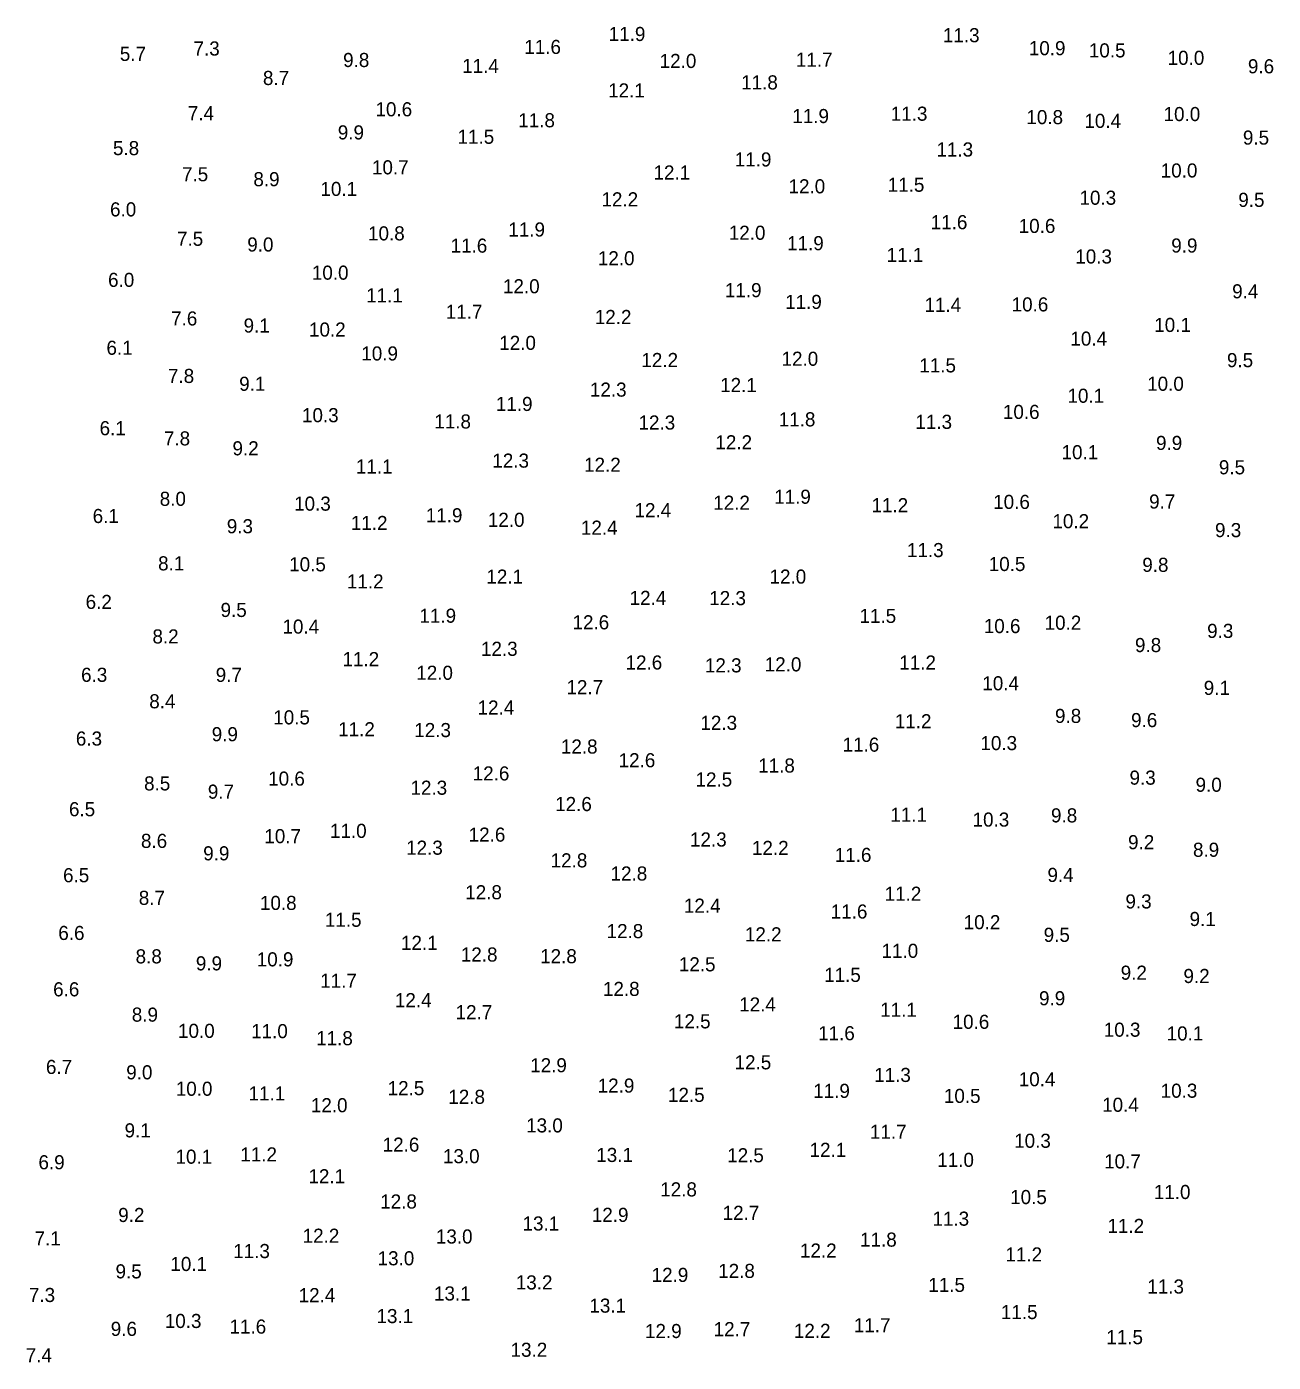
# Model space of a CAD drawing. Extents: x 1023796 to 1112670, y 656573 to 837340.
# Drawn here: x 1112085.5 to 1112527.9, y 658444 to 658917.7 of the extents above; entities that cross this region are included whole.
import ezdxf

# ---------------------------------------------------------------- set-up
doc = ezdxf.new("R2010")
doc.units = 0
doc.layers.add('V-TOPO-SOUN', color=7, linetype='Continuous')

msp = doc.modelspace()

# ---------------------------------------------------------------- texts
at = {"layer": 'V-TOPO-SOUN'}
for s, p in [('11.9 ', (1112292.06, 658912.64)), ('11.3 ', (1112410.64, 658912.21)), ('5.7', (1112118.58, 658905.59)), ('7.3', (1112144.73, 658907.49)), ('11.6 ', (1112262.1, 658908.05)), ('10.9 ', (1112441.13, 658907.61)), ('10.5 ', (1112462.43, 658906.82)), ('10.0 ', (1112490.39, 658904.19)), ('9.8', (1112197.82, 658903.41)), ('11.4 ', (1112240.06, 658901.3)), ('12.0 ', (1112310.14, 658903.07)), ('11.7 ', (1112358.47, 658903.52)), ('9.6', (1112518.88, 658901.18)), ('8.7', (1112169.36, 658897.03)), ('11.8 ', (1112339.05, 658895.47)), ('12.1 ', (1112291.86, 658892.62)), ('10.6 ', (1112209.3, 658885.93)), ('7.4', (1112142.72, 658884.55)), ('11.8 ', (1112259.96, 658882.03)), ('11.9 ', (1112357.2, 658883.53)), ('11.3 ', (1112392.14, 658884.36)), ('10.8 ', (1112440.27, 658883.15)), ('10.4 ', (1112460.86, 658881.82)), ('10.0 ', (1112488.95, 658884.24)), ('9.9', (1112195.93, 658877.73)), ('11.5 ', (1112238.41, 658876.18)), ('9.5', (1112517.1, 658875.89)), ('5.8', (1112116.14, 658872.16)), ('11.3 ', (1112408.35, 658871.67)), ('11.9 ', (1112336.78, 658868.14)), ('7.5', (1112140.65, 658862.89)), ('8.9', (1112165.97, 658861.14)), ('10.7 ', (1112208.05, 658865.34)), ('12.1 ', (1112307.95, 658863.51)), ('10.0 ', (1112487.94, 658864.23)), ('10.1 ', (1112189.76, 658857.69)), ('12.0 ', (1112355.86, 658858.61)), ('11.5 ', (1112391.06, 658859.17)), ('12.2 ', (1112289.48, 658853.98)), ('10.3 ', (1112459.11, 658854.56)), ('9.5', (1112515.46, 658853.81)), ('6.0', (1112115.11, 658850.43)), ('11.9 ', (1112256.44, 658843.29)), ('12.0 ', (1112334.66, 658842.14)), ('11.6 ', (1112406.32, 658845.88)), ('10.6 ', (1112437.54, 658844.56)), ('7.5', (1112138.86, 658840)), ('9.0', (1112163.8, 658837.98)), ('10.8 ', (1112206.66, 658841.92)), ('11.6 ', (1112235.96, 658837.57)), ('11.9 ', (1112355.35, 658838.44)), ('9.9', (1112491.67, 658837.61)), ('12.0 ', (1112288.2, 658833.09)), ('11.1 ', (1112390.68, 658834.28)), ('10.3 ', (1112457.62, 658833.72)), ('10.0 ', (1112186.72, 658827.98)), ('6.0', (1112114.41, 658825.43)), ('11.1 ', (1112205.97, 658819.94)), ('12.0 ', (1112254.54, 658823.16)), ('11.9 ', (1112333.29, 658821.78)), ('9.4', (1112513.29, 658821.37)), ('11.7 ', (1112234.23, 658814.11)), ('11.9 ', (1112354.66, 658817.61)), ('11.4 ', (1112404.11, 658816.57)), ('10.6 ', (1112435.04, 658816.73)), ('7.6', (1112136.78, 658811.75)), ('9.1', (1112162.5, 658809.24)), ('12.2 ', (1112287.11, 658812.25)), ('10.1 ', (1112485.64, 658809.44)), ('10.2 ', (1112185.71, 658807.81)), ('10.4 ', (1112455.88, 658804.59)), ('6.1', (1112113.84, 658801.35)), ('12.0 ', (1112253.21, 658803.09)), ('10.9 ', (1112204.27, 658799.33)), ('12.2 ', (1112303.65, 658797)), ('12.0 ', (1112353.39, 658797.45)), ('11.5 ', (1112402.27, 658795.11)), ('9.5', (1112511.44, 658796.96)), ('7.8', (1112135.66, 658791.35)), ('9.1', (1112160.94, 658788.58)), ('12.3 ', (1112285.38, 658786.5)), ('12.1 ', (1112331.6, 658788.14)), ('10.0 ', (1112483.12, 658788.58)), ('11.9 ', (1112252.02, 658781.42)), ('10.1 ', (1112454.85, 658784.33)), ('10.3 ', (1112183.22, 658777.44)), ('11.8 ', (1112352.39, 658775.96)), ('10.6 ', (1112431.93, 658778.6)), ('6.1', (1112111.4, 658772.82)), ('11.8 ', (1112230.17, 658775.21)), ('12.3 ', (1112302.63, 658774.83)), ('11.3 ', (1112400.88, 658775.08)), ('7.8', (1112134.22, 658769.2)), ('12.2 ', (1112329.91, 658767.82)), ('9.9', (1112486.27, 658767.6)), ('9.2', (1112158.56, 658765.68)), ('10.1 ', (1112452.75, 658764.31)), ('11.1 ', (1112202.35, 658759.23)), ('12.3 ', (1112250.76, 658761.32)), ('12.2 ', (1112283.32, 658759.85)), ('9.5', (1112508.58, 658758.95)), ('8.0', (1112132.73, 658747.78)), ('11.9 ', (1112350.77, 658748.5)), ('10.3 ', (1112180.42, 658746.06)), ('12.4 ', (1112301.21, 658743.74)), ('12.2 ', (1112329.14, 658746.39)), ('11.2 ', (1112385.3, 658745.5)), ('10.6 ', (1112428.49, 658746.68)), ('9.7', (1112483.83, 658746.81)), ('6.1', (1112108.94, 658741.68)), ('9.3', (1112156.54, 658738.05)), ('11.2 ', (1112200.54, 658739.2)), ('11.9 ', (1112227.14, 658741.93)), ('12.0 ', (1112249.17, 658740.33)), ('10.2 ', (1112449.51, 658739.83)), ('12.4 ', (1112282.19, 658737.54)), ('9.3', (1112507.21, 658736.67)), ('11.3 ', (1112397.9, 658729.59)), ('8.1', (1112132.17, 658724.88)), ('10.5 ', (1112178.67, 658724.54)), ('10.5 ', (1112426.91, 658724.65)), ('9.8', (1112481.39, 658724.36)), ('12.1 ', (1112248.65, 658720.17)), ('12.0 ', (1112349.13, 658720.18)), ('11.2 ', (1112199.15, 658718.46)), ('6.2', (1112106.45, 658711.21)), ('12.4 ', (1112299.48, 658712.63)), ('12.3 ', (1112327.73, 658712.55)), ('9.5', (1112154.33, 658708.35)), ('11.9 ', (1112224.89, 658706.31)), ('11.5 ', (1112381.05, 658706.24)), ('10.4 ', (1112176.29, 658702.45)), ('12.6 ', (1112279.21, 658703.97)), ('10.6 ', (1112425.15, 658702.64)), ('10.2 ', (1112446.74, 658703.83)), ('9.3', (1112504.41, 658700.93)), ('8.2', (1112130.16, 658698.96)), ('9.8', (1112478.8, 658695.9)), ('11.2 ', (1112197.59, 658690.91)), ('12.3 ', (1112246.73, 658694.57)), ('12.0 ', (1112223.77, 658686.07)), ('12.6 ', (1112298.03, 658689.72)), ('12.3 ', (1112326.19, 658688.7)), ('12.0 ', (1112347.42, 658689.06)), ('11.2 ', (1112395.16, 658689.7)), ('6.3', (1112104.83, 658685.35)), ('9.7', (1112152.61, 658685.33)), ('10.4 ', (1112424.63, 658682.34)), ('12.7 ', (1112277.06, 658680.95)), ('9.1', (1112503.2, 658680.72)), ('8.4', (1112129.03, 658675.96)), ('12.4 ', (1112245.53, 658673.74)), ('10.5 ', (1112173.02, 658670.26)), ('12.3 ', (1112324.6, 658668.33)), ('11.2 ', (1112393.57, 658668.88)), ('9.8', (1112450.42, 658670.77)), ('9.6', (1112477.42, 658669.29)), ('6.3', (1112102.98, 658662.74)), ('9.9', (1112151.19, 658664.29)), ('11.2 ', (1112196.05, 658666.03)), ('12.3 ', (1112223.06, 658665.75)), ('12.8 ', (1112275.09, 658659.91)), ('11.6 ', (1112375.06, 658660.58)), ('10.3 ', (1112423.96, 658661.13)), ('12.6 ', (1112295.58, 658655.05)), ('11.8 ', (1112345.09, 658653.18)), ('10.6 ', (1112171.22, 658648.54)), ('12.6 ', (1112243.8, 658650.37)), ('12.5 ', (1112322.86, 658648.23)), ('9.3', (1112476.87, 658648.87)), ('8.5', (1112127.19, 658646.83)), ('9.7', (1112149.81, 658643.9)), ('12.3 ', (1112221.72, 658645.3)), ('9.0', (1112500.3, 658646.36)), ('12.6 ', (1112273.05, 658639.51)), ('6.5', (1112100.53, 658637.68)), ('11.1 ', (1112392, 658635.74)), ('10.3 ', (1112421.18, 658634)), ('9.8', (1112449, 658635.49)), ('11.0 ', (1112193.15, 658630)), ('8.6', (1112126.08, 658626.45)), ('10.7 ', (1112169.86, 658628.13)), ('12.6 ', (1112242.37, 658628.67)), ('12.3 ', (1112320.91, 658626.94)), ('9.2', (1112476.35, 658625.99)), ('9.9', (1112148.17, 658622.03)), ('12.3 ', (1112220.17, 658624.03)), ('12.8 ', (1112271.46, 658619.54)), ('12.2 ', (1112342.89, 658623.94)), ('11.6 ', (1112372.27, 658621.47)), ('8.9', (1112499.38, 658623.3)), ('12.8 ', (1112292.72, 658614.88)), ('6.5', (1112098.43, 658614.27)), ('9.4', (1112447.75, 658614.38)), ('8.7', (1112125.31, 658606.25)), ('12.8 ', (1112241.14, 658608.22)), ('11.2 ', (1112389.98, 658607.7)), ('10.8 ', (1112168.3, 658604.44)), ('12.4 ', (1112318.73, 658603.46)), ('11.6 ', (1112370.84, 658601.39)), ('9.3', (1112475.42, 658604.97)), ('11.5 ', (1112191.34, 658598.47)), ('10.2 ', (1112418.02, 658597.61)), ('9.1', (1112498.18, 658598.74)), ('6.6', (1112096.75, 658593.79)), ('12.8 ', (1112291.31, 658594.44)), ('12.2 ', (1112340.38, 658593.3)), ('9.5', (1112446.4, 658593.13)), ('12.1 ', (1112218.35, 658590.28)), ('11.0 ', (1112388.87, 658587.46)), ('8.8', (1112124.18, 658585.49)), ('9.9', (1112145.56, 658583)), ('10.9 ', (1112167.17, 658584.43)), ('12.8 ', (1112239.58, 658586.14)), ('12.8 ', (1112267.72, 658585.54)), ('12.5 ', (1112316.94, 658582.67)), ('11.5 ', (1112368.5, 658578.92)), ('9.2', (1112473.73, 658579.69)), ('9.2', (1112496.01, 658578.52)), ('6.6', (1112094.92, 658573.8)), ('11.7 ', (1112189.67, 658576.85)), ('12.8 ', (1112290.02, 658573.94)), ('12.4 ', (1112216.18, 658569.95)), ('12.4 ', (1112338.36, 658568.43)), ('9.9', (1112444.76, 658570.63)), ('8.9', (1112122.83, 658564.82)), ('12.7 ', (1112237.72, 658565.69)), ('11.1 ', (1112388.38, 658566.56)), ('10.0 ', (1112139.23, 658559.07)), ('11.0 ', (1112165.17, 658558.97)), ('12.5 ', (1112315.2, 658562.45)), ('11.6 ', (1112366.36, 658558.22)), ('10.6 ', (1112414.09, 658562.28)), ('10.3 ', (1112467.72, 658559.48)), ('10.1 ', (1112490.04, 658558.15)), ('11.8 ', (1112188.24, 658556.47)), ('6.7', (1112092.36, 658546.27)), ('9.0', (1112120.85, 658544.36)), ('12.9 ', (1112264.19, 658546.87)), ('12.5 ', (1112336.72, 658547.91)), ('12.9 ', (1112288.15, 658539.65)), ('11.3 ', (1112386.25, 658543.43)), ('10.4 ', (1112437.56, 658541.91)), ('10.0 ', (1112138.43, 658538.53)), ('11.1 ', (1112164.26, 658536.87)), ('12.5 ', (1112213.62, 658538.75)), ('12.8 ', (1112235.15, 658535.67)), ('12.5 ', (1112313.09, 658536.36)), ('11.9 ', (1112364.63, 658537.79)), ('10.5 ', (1112410.99, 658535.99)), ('10.3 ', (1112487.92, 658537.84)), ('12.0 ', (1112186.37, 658532.69)), ('10.4 ', (1112467.15, 658532.85)), ('13.0 ', (1112262.76, 658525.53)), ('9.1', (1112120.27, 658523.77)), ('11.7 ', (1112384.75, 658523.27)), ('10.3 ', (1112435.93, 658520.08)), ('12.6 ', (1112211.85, 658518.71)), ('12.1 ', (1112363.33, 658516.86)), ('6.9', (1112089.71, 658512.46)), ('10.1 ', (1112138.34, 658514.44)), ('11.2 ', (1112161.34, 658515.24)), ('13.0 ', (1112233.24, 658514.62)), ('13.1 ', (1112287.64, 658515.05)), ('12.5 ', (1112334.09, 658514.94)), ('11.0 ', (1112408.64, 658513.31)), ('10.7 ', (1112467.85, 658512.77)), ('12.1 ', (1112185.51, 658507.49)), ('12.8 ', (1112310.33, 658502.84)), ('11.0 ', (1112485.48, 658501.91)), ('12.8 ', (1112210.97, 658498.55)), ('10.5 ', (1112434.51, 658500.12)), ('9.2', (1112118.01, 658493.76)), ('12.9 ', (1112286.06, 658493.81)), ('12.7 ', (1112332.49, 658494.52)), ('11.3 ', (1112406.94, 658492.45)), ('13.1 ', (1112261.48, 658490.74)), ('11.2 ', (1112469.03, 658489.88)), ('7.1', (1112088.33, 658485.46)), ('12.2 ', (1112183.46, 658486.4)), ('13.0 ', (1112230.73, 658486.13)), ('11.8 ', (1112381.25, 658485.02)), ('11.3 ', (1112158.82, 658480.97)), ('13.0 ', (1112210.05, 658478.4)), ('12.2 ', (1112359.93, 658481.14)), ('11.2 ', (1112432.83, 658479.76)), ('9.5', (1112117.06, 658473.76)), ('10.1 ', (1112136.52, 658476.38)), ('12.8 ', (1112330.9, 658473.92)), ('13.2 ', (1112259.09, 658469.84)), ('12.9 ', (1112307.29, 658472.51)), ('11.5 ', (1112405.47, 658468.96)), ('11.3 ', (1112483.18, 658468.39)), ('7.3', (1112086.32, 658465.39)), ('12.4 ', (1112182.04, 658465.33)), ('13.1 ', (1112230.06, 658465.92)), ('13.1 ', (1112285.21, 658461.61)), ('11.5 ', (1112431.23, 658459.34)), ('10.3 ', (1112134.53, 658456.17)), ('11.6 ', (1112157.5, 658454.17)), ('13.1 ', (1112209.66, 658457.9)), ('11.7 ', (1112379.03, 658454.64)), ('9.6', (1112115.36, 658453.37)), ('12.9 ', (1112304.94, 658452.6)), ('12.7 ', (1112329.3, 658453.27)), ('12.2 ', (1112357.76, 658452.66)), ('11.5 ', (1112468.63, 658450.43)), ('13.2 ', (1112257.23, 658445.95)), ('7.4', (1112085.19, 658444.01))]:
    msp.add_text(s, height=5, dxfattribs=at).set_placement(p)

doc.saveas('drawing.dxf')
